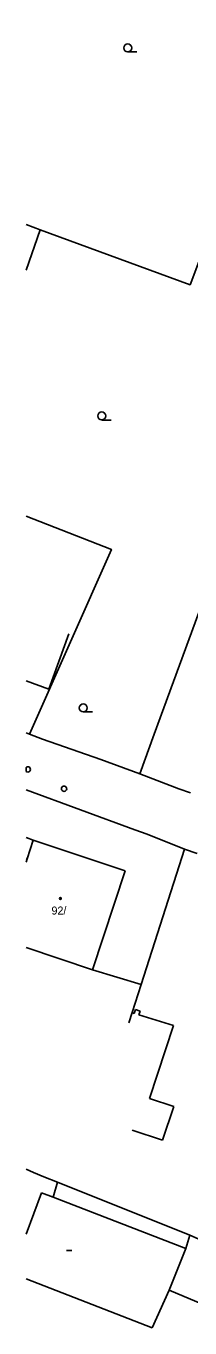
# Model space of a CAD drawing. Extents: x -737812 to -729375, y -1123000 to -1115500.
# Drawn here: x -736891.1 to -736875.7, y -1118695.1 to -1118573.1 of the extents above; entities that cross this region are included whole.
import ezdxf

# ---------------------------------------------------------------- set-up
doc = ezdxf.new("R2010")
doc.units = 0
for name, color, linetype in [('Hranice - ploty_ zdi', 7, 'Continuous'), ('Hranice parcel a úz_ celk', 7, 'Continuous'), ('Povr_ zn_ inž_ sítí - vod_', 7, 'Continuous'), ('Stavební objekty', 7, 'Continuous'), ('Značky druhů budov', 7, 'Continuous'), ('Značky druhů pozemků', 7, 'Continuous'), ('Čísla popisná', 7, 'Continuous')]:
    doc.layers.add(name, color=color, linetype=linetype)

msp = doc.modelspace()

# ---------------------------------------------------------------- linework, layer by layer
at = {"layer": 'Hranice - ploty_ zdi'}
msp.add_line((-736889.4, -1118680.89), (-736890.39, -1118680.47), dxfattribs=at)
for points in [[(-736891.08, -1118639.29), (-736890.76, -1118639.41)], [(-736889.55, -1118639.86), (-736890.76, -1118639.41)], [(-736889.55, -1118639.86), (-736884.07, -1118641.78)], [(-736880.4, -1118643.12), (-736879.05, -1118639.4)], [(-736884.07, -1118641.78), (-736880.4, -1118643.12)], [(-736880.4, -1118643.12), (-736876.75, -1118644.54), (-736875.64, -1118644.91)], [(-736880.88, -1118648.38), (-736891.08, -1118644.63)], [(-736876.2, -1118650.18), (-736879.72, -1118648.78), (-736880.88, -1118648.38)], [(-736875.02, -1118650.59), (-736876.2, -1118650.18)], [(-736891.08, -1118680.17), (-736890.39, -1118680.47)], [(-736889.4, -1118680.89), (-736888.14, -1118681.38), (-736888.53, -1118682.79)]]:
    msp.add_lwpolyline(points, dxfattribs=at)
at = {"layer": 'Hranice parcel a úz_ celk'}
for points in [[(-736891.08, -1118591.65), (-736889.75, -1118592.15), (-736875.68, -1118597.3), (-736869.32, -1118580.46), (-736864.7, -1118568.04)], [(-736891.08, -1118595.94), (-736889.75, -1118592.15)], [(-736891.08, -1118618.97), (-736883.07, -1118622.09), (-736890.76, -1118639.41)], [(-736879.05, -1118639.4), (-736874.86, -1118628.01)], [(-736890.4, -1118649.34), (-736891.08, -1118649.09)], [(-736876.2, -1118650.18), (-736880.29, -1118662.88), (-736881.13, -1118665.5)], [(-736884.84, -1118661.5), (-736880.29, -1118662.88)], [(-736888.14, -1118681.38), (-736875.71, -1118686.37)]]:
    msp.add_lwpolyline(points, dxfattribs=at)
at = {"layer": 'Povr_ zn_ inž_ sítí - vod_'}
msp.add_line((-736891.08, -1118642.52), (-736891.08, -1118642.9), dxfattribs=at)
msp.add_circle((-736887.51, -1118644.52), 0.25, dxfattribs=at)
msp.add_arc((-736890.92, -1118642.71), 0.25, 229.0194, 130.9806, dxfattribs=at)
at = {"layer": 'Stavební objekty'}
for p, q in [((-736888.93, -1118635.19), (-736887.07, -1118630)), ((-736888.93, -1118635.19), (-736891.08, -1118634.42)), ((-736890.4, -1118649.34), (-736890.99, -1118651.1)), ((-736881.79, -1118652.22), (-736890.4, -1118649.34)), ((-736890.99, -1118651.1), (-736891.08, -1118651.07))]:
    msp.add_line(p, q, dxfattribs=at)
for points in [[(-736891.08, -1118651.39), (-736890.99, -1118651.1)], [(-736881.79, -1118652.22), (-736884.84, -1118661.5), (-736891.08, -1118659.41)], [(-736881.13, -1118665.5), (-736881.42, -1118666.46)], [(-736880.92, -1118665.57), (-736881.13, -1118665.5)], [(-736880.82, -1118665.2), (-736880.92, -1118665.57)], [(-736880.82, -1118665.2), (-736880.38, -1118665.35)], [(-736880.38, -1118665.35), (-736880.49, -1118665.7)], [(-736877.23, -1118666.7), (-736880.49, -1118665.7)], [(-736879.49, -1118673.55), (-736877.23, -1118666.7)], [(-736877.22, -1118674.3), (-736879.49, -1118673.55)], [(-736878.26, -1118677.45), (-736877.22, -1118674.3)], [(-736878.26, -1118677.45), (-736881.11, -1118676.51)], [(-736891.08, -1118686.26), (-736889.62, -1118682.38)], [(-736889.62, -1118682.38), (-736888.53, -1118682.79), (-736876.09, -1118687.61)], [(-736875.71, -1118686.37), (-736876.09, -1118687.61), (-736877.65, -1118691.52), (-736879.26, -1118695.05)], [(-736869.72, -1118689.02), (-736875.71, -1118686.37)], [(-736879.26, -1118695.05), (-736891.08, -1118690.46)], [(-736871.85, -1118693.95), (-736877.65, -1118691.52)]]:
    msp.add_lwpolyline(points, dxfattribs=at)
at = {"layer": 'Značky druhů budov'}
msp.add_line((-736887.28, -1118687.79), (-736886.78, -1118687.79), dxfattribs=at)
msp.add_circle((-736887.86, -1118654.81), 0.0875, dxfattribs=at)
at = {"layer": 'Značky druhů pozemků'}
for p, q in [((-736881.54, -1118575.48), (-736880.67, -1118575.48)), ((-736883.98, -1118609.97), (-736883.1, -1118609.97)), ((-736885.71, -1118637.32), (-736884.83, -1118637.32))]:
    msp.add_line(p, q, dxfattribs=at)
for centre in [(-736881.54, -1118575.1), (-736883.98, -1118609.59), (-736885.71, -1118636.95)]:
    msp.add_circle(centre, 0.375, dxfattribs=at)

# ---------------------------------------------------------------- texts
at = {"layer": 'Čísla popisná'}
msp.add_text('92/', height=0.75, dxfattribs=at).set_placement((-736888.69, -1118656.31))

doc.saveas('drawing.dxf')
